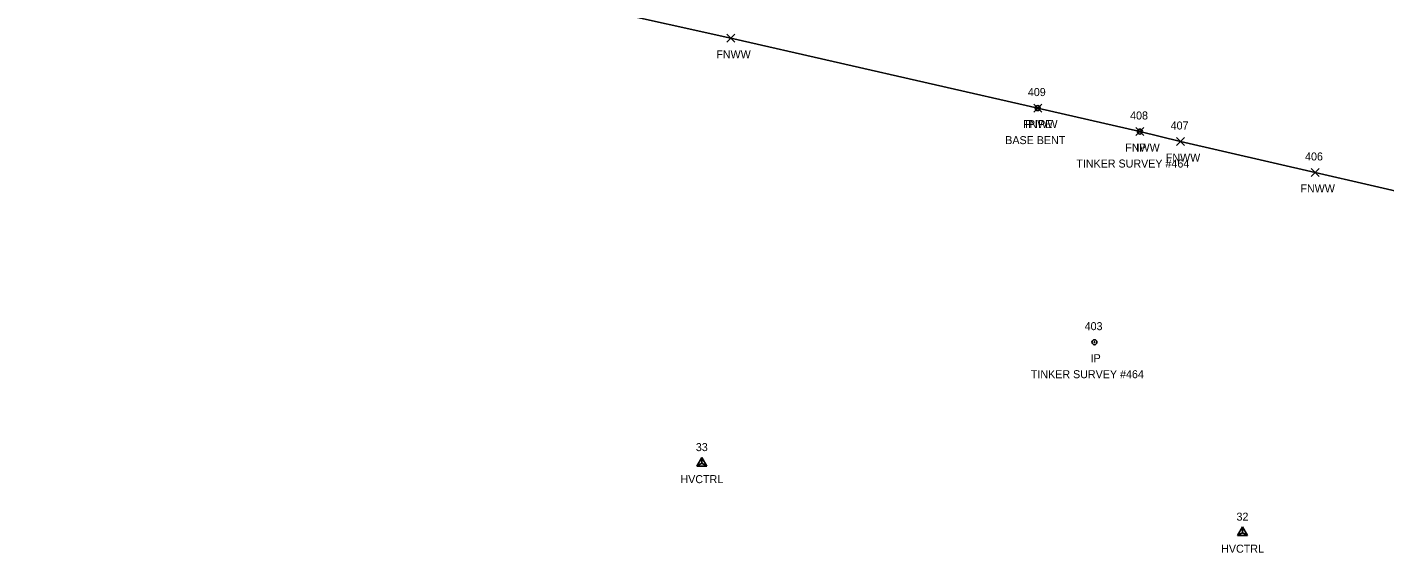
# Model space of a CAD drawing. Extents: x 1509053 to 1511576, y 400838 to 402572.
# Drawn here: x 1509229.4 to 1509568.8, y 401292.1 to 401423.4 of the extents above; entities that cross this region are included whole.
import ezdxf

# ---------------------------------------------------------------- set-up
doc = ezdxf.new("R2010")
doc.units = 0
for name, color, linetype in [('C_A', 7, 'Continuous'), ('C_I', 7, 'Continuous'), ('CPSM', 7, 'Continuous'), ('L_A', 7, 'Continuous'), ('L_I', 7, 'Continuous'), ('L_TIC', 7, 'Continuous'), ('LFNC', 7, 'Continuous'), ('M_A', 7, 'Continuous'), ('M_C', 7, 'Continuous'), ('M_I', 7, 'Continuous'), ('MPIP', 7, 'Continuous'), ('MPIR', 7, 'Continuous')]:
    doc.layers.add(name, color=color, linetype=linetype)

msp = doc.modelspace()

# ---------------------------------------------------------------- linework, layer by layer
at = {"layer": 'CPSM'}
for p, q in [((1509396.77, 401313.76), (1509398.02, 401315.93)), ((1509399.27, 401313.76), (1509398.02, 401315.93)), ((1509398.02, 401314.49), (1509398.02, 401315.93)), ((1509396.77, 401313.76), (1509398.02, 401314.49)), ((1509396.77, 401313.76), (1509399.27, 401313.76)), ((1509398.02, 401314.49), (1509398.02, 401314.49)), ((1509398.02, 401314.49), (1509399.27, 401313.76)), ((1509531.91, 401296.4), (1509533.16, 401298.56)), ((1509534.41, 401296.4), (1509533.16, 401298.56)), ((1509533.16, 401297.12), (1509533.16, 401298.56)), ((1509531.91, 401296.4), (1509533.16, 401297.12)), ((1509531.91, 401296.4), (1509534.41, 401296.4)), ((1509533.16, 401297.12), (1509533.16, 401297.12)), ((1509533.16, 401297.12), (1509534.41, 401296.4))]:
    msp.add_line(p, q, dxfattribs=at)
at = {"layer": 'L_TIC'}
for points in [[(1509404.33, 401419.58), (1509406.33, 401421.58)], [(1509406.33, 401419.58), (1509404.33, 401421.58)], [(1509481, 401402.15), (1509483, 401404.15)], [(1509483, 401402.15), (1509481, 401404.15)], [(1509506.55, 401396.3), (1509508.55, 401398.3)], [(1509508.55, 401396.3), (1509506.55, 401398.3)], [(1509516.68, 401393.8), (1509518.68, 401395.8)], [(1509518.68, 401393.8), (1509516.68, 401395.8)], [(1509550.33, 401386.07), (1509552.33, 401388.07)], [(1509552.33, 401386.07), (1509550.33, 401388.07)]]:
    msp.add_lwpolyline(points, dxfattribs=at)
at = {"layer": 'LFNC'}
msp.add_lwpolyline([(1509653.22, 401364.75), (1509592.63, 401377.6), (1509551.33, 401387.07), (1509517.68, 401394.8), (1509507.55, 401397.3), (1509482, 401403.15), (1509405.33, 401420.58), (1509342.12, 401434.67), (1509296.16, 401445.22), (1509229.42, 401460.13)], dxfattribs=at)
at = {"layer": 'MPIP'}
for radius in [0.625, 0.0833]:
    msp.add_circle((1509482, 401403.15), radius, dxfattribs=at)
at = {"layer": 'MPIR'}
for centre, radius in [((1509507.55, 401397.3), 0.625), ((1509507.55, 401397.3), 0.0833), ((1509496.19, 401344.69), 0.625), ((1509496.19, 401344.69), 0.0833)]:
    msp.add_circle(centre, radius, dxfattribs=at)

# ---------------------------------------------------------------- texts
at = {"layer": 'C_A'}
for p in [(1509392.71, 401309.49), (1509527.86, 401292.12)]:
    msp.add_text('HVCTRL', height=2, dxfattribs=at).set_placement(p)
at = {"layer": 'C_I'}
for s, p in [('33', (1509396.56, 401317.49)), ('32', (1509531.7, 401300.12))]:
    msp.add_text(s, height=2, dxfattribs=at).set_placement(p)
at = {"layer": 'L_A'}
for p in [(1509401.67, 401415.58), (1509478.35, 401398.15), (1509503.9, 401392.3), (1509514.03, 401389.8), (1509547.68, 401382.07)]:
    msp.add_text('FNWW', height=2, dxfattribs=at).set_placement(p)
at = {"layer": 'L_I'}
for s, p in [('409', (1509479.55, 401406.15)), ('408', (1509505.11, 401400.3)), ('407', (1509515.24, 401397.8)), ('406', (1509548.84, 401390.07))]:
    msp.add_text(s, height=2, dxfattribs=at).set_placement(p)
at = {"layer": 'M_A'}
for s, p in [('IPIPE', (1509478.83, 401398.15)), ('IP', (1509506.6, 401392.3)), ('IP', (1509495.24, 401339.69))]:
    msp.add_text(s, height=2, dxfattribs=at).set_placement(p)
at = {"layer": 'M_C'}
for s, p in [('BASE BENT', (1509473.9, 401394.15)), ('TINKER SURVEY #464', (1509491.66, 401388.3)), ('TINKER SURVEY #464', (1509480.3, 401335.69))]:
    msp.add_text(s, height=2, dxfattribs=at).set_placement(p)
at = {"layer": 'M_I'}
for s, p in [('409', (1509479.55, 401406.15)), ('408', (1509505.11, 401400.3)), ('403', (1509493.75, 401347.69))]:
    msp.add_text(s, height=2, dxfattribs=at).set_placement(p)

doc.saveas('drawing.dxf')
